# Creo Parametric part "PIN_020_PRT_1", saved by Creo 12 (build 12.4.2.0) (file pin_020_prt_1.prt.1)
Units: Custom; MM, KILOGRAM, SECS

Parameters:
  PTC_WM_ITERATION = "0"
  PTC_WM_VERSION = "-.0"
  PTC_WM_LIFECYCLE_STATE = "In Work"
  PTC_WM_LIFECYCLE = "MO_CADDocument"
  PTC_WM_CREATED_BY = "Maximilian Roepper (Z0017RMS: MO)"
  PTC_WM_CREATED_ON = "18-Sep-26 11:36:42 AM"
  PTC_WM_MODIFIED_BY = "Maximilian Roepper (Z0017RMS: MO)"
  PTC_WM_MODIFIED_ON = "18-Sep-26 11:36:46 AM"
  PDMLINKNUMBER = "PDM000071454880"
  PTC_WM_NAME = "pin_020_prt_1.prt"
  PTC_WM_NUMBER = "PDM000071454880"

Other parameters: WEIGHT, WEIGHT_FACTOR, WEIGHT_ADD, _MASS_TEMP, _DIFF_TEMP, MC_ERRORS, SUPPLIER

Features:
  1. coordinate system
  2. datum plane "PRT_YZ"
  3. datum plane "PRT_XY"
  4. datum plane "PRT_XZ"
  5. coordinate system
  6. datum axis
  7. datum axis
  8. datum axis
  9. coordinate system
  10. imported feature
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
Other named items: PRT, SIEMENS_MO, DRW_VIEW_ORG, PRT_X, PRT_Y, PRT_Z, CS0, ROUGH_GROB

Layers: 00_STD_CSYS-KSYS, 01_STD_PLANES-EBENEN, 02_STD_AXES-ACHSEN, 03_STD_CSYS-KSYS, 24_IMPORT_FEAT-IMPORT_KE

Surfaces: 9 plane, 1 cylinder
